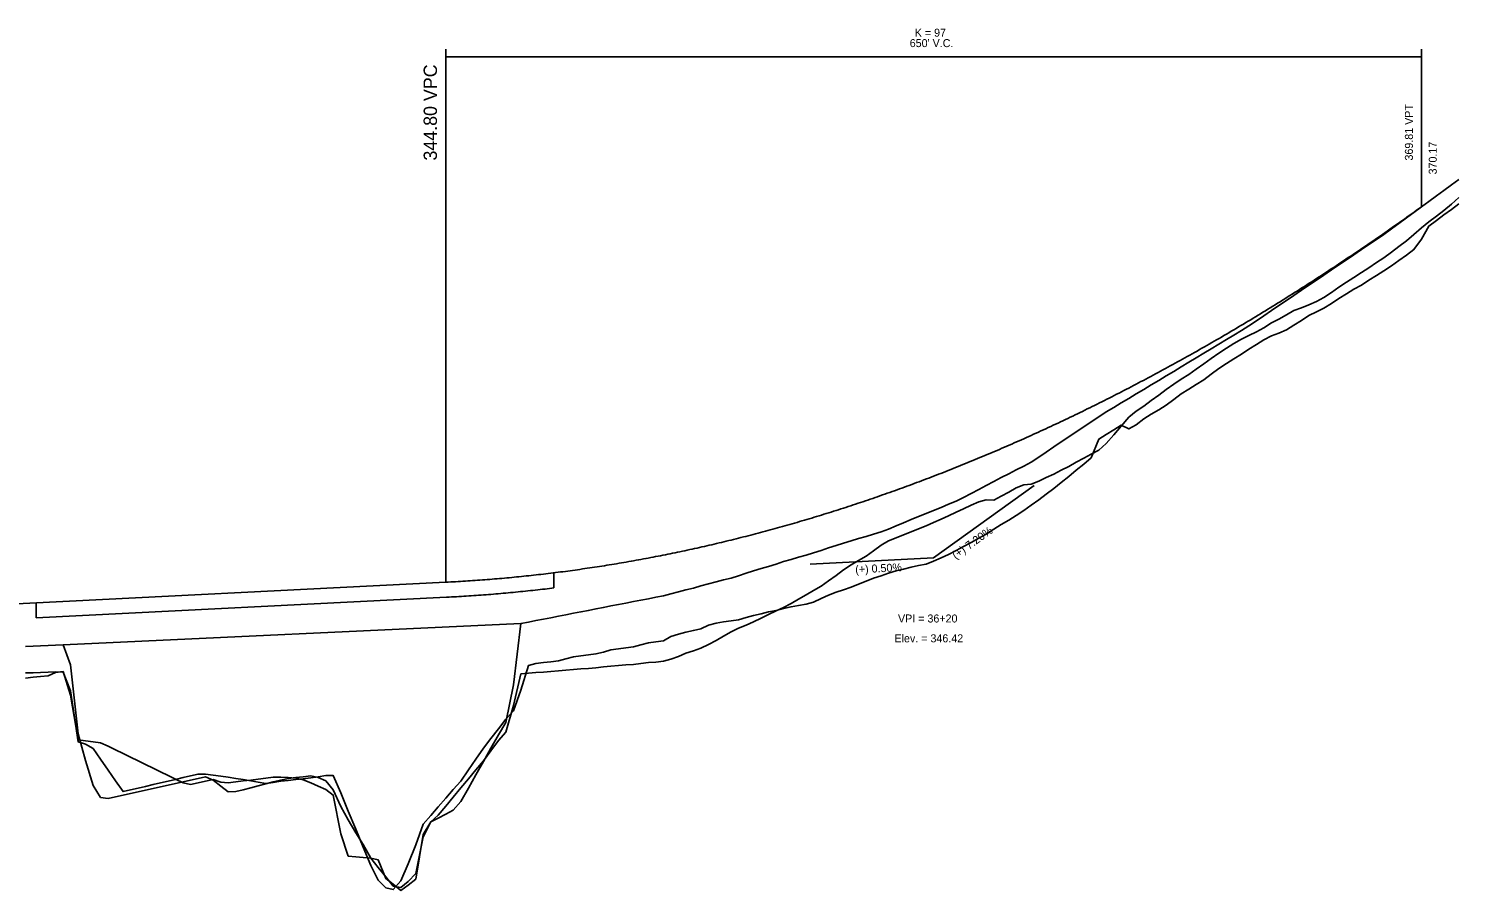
# Model space of a CAD drawing. Extents: x 2005261 to 2010661, y 1001568 to 1006764.
# Drawn here: x 2007639 to 2008591, y 1004311 to 1004885 of the extents above; entities that cross this region are included whole.
import ezdxf

# ---------------------------------------------------------------- set-up
doc = ezdxf.new("R2010")
doc.units = 0
for name, color, linetype in [('RD_DDB_GradeTX', 7, 'Continuous'), ('RD_DDB_Profile_EX', 7, 'Continuous'), ('RD_DDB_Profile_Lbl', 7, 'Continuous'), ('RD_DDB_Profile_PR', 7, 'Continuous'), ('RD_DDB_StripGrade', 7, 'Continuous'), ('RD_DDB_VCLbl', 7, 'Continuous'), ('RD_PD_Bridge', 7, 'Continuous'), ('RD_Sketch1', 7, 'Continuous'), ('RD_Sketch2', 7, 'Continuous'), ('RD_Sketch3', 7, 'Continuous')]:
    doc.layers.add(name, color=color, linetype=linetype)

msp = doc.modelspace()

# ---------------------------------------------------------------- linework, layer by layer
at = {"layer": 'RD_DDB_GradeTX'}
for p in [(2008308.61, 1004580.73), (2008159.44, 1004528.49)]:
    msp.add_line(p, (2008241.73, 1004532.6), dxfattribs=at)
at = {"layer": 'RD_DDB_Profile_EX'}
for points in [[(2008176.73, 1004540.77), (2008181.73, 1004542.33), (2008186.73, 1004543.87), (2008191.73, 1004545.4), (2008196.73, 1004546.9), (2008201.73, 1004548.39), (2008206.73, 1004549.86), (2008211.73, 1004551.71), (2008216.73, 1004553.84), (2008221.73, 1004555.96), (2008226.73, 1004558.06), (2008231.73, 1004560.14), (2008236.73, 1004562.18), (2008241.73, 1004564.23), (2008246.73, 1004566.26), (2008251.73, 1004568.27), (2008256.73, 1004570.27), (2008261.73, 1004572.79), (2008266.73, 1004575.47), (2008271.73, 1004578.14), (2008276.73, 1004580.79), (2008281.73, 1004583.43), (2008286.73, 1004586.04), (2008291.73, 1004588.65), (2008296.73, 1004591.22), (2008301.73, 1004593.75), (2008306.73, 1004596.27), (2008311.73, 1004599.67), (2008316.73, 1004603.1), (2008321.73, 1004606.51), (2008326.73, 1004609.9), (2008331.73, 1004613.27), (2008336.73, 1004616.62), (2008341.73, 1004619.97), (2008346.73, 1004623.32), (2008351.73, 1004626.67), (2008356.73, 1004629.81), (2008361.73, 1004632.81), (2008366.73, 1004635.8), (2008371.73, 1004638.8), (2008376.73, 1004641.79), (2008381.73, 1004644.88), (2008386.73, 1004647.87), (2008391.73, 1004650.87), (2008396.73, 1004653.86), (2008401.73, 1004656.86), (2008406.73, 1004659.94), (2008411.73, 1004662.94), (2008416.73, 1004665.94), (2008421.73, 1004668.93), (2008426.73, 1004671.93), (2008431.73, 1004675.01), (2008436.73, 1004678.01), (2008441.73, 1004681.01), (2008446.73, 1004684), (2008451.73, 1004687.19), (2008456.73, 1004690.58), (2008461.73, 1004693.97), (2008466.73, 1004697.35), (2008471.73, 1004700.74), (2008476.73, 1004704.13), (2008481.73, 1004707.52), (2008486.73, 1004710.9), (2008491.73, 1004714.29), (2008496.73, 1004717.68), (2008501.73, 1004721.07), (2008506.73, 1004724.45), (2008511.73, 1004727.84), (2008516.73, 1004731.22), (2008521.73, 1004734.61), (2008526.73, 1004738), (2008531.73, 1004741.38), (2008536.73, 1004744.77), (2008541.73, 1004748.16), (2008546.73, 1004751.74), (2008551.73, 1004755.41), (2008556.73, 1004759.09), (2008561.73, 1004762.76), (2008566.73, 1004766.43), (2008571.73, 1004770.1), (2008576.73, 1004773.77), (2008581.73, 1004777.45), (2008586.73, 1004781.12), (2008591.73, 1004784.79)], [(2007676.73, 1004397.66), (2007681.73, 1004380.82), (2007686.73, 1004372.92), (2007691.73, 1004372.21), (2007696.73, 1004373.33), (2007701.73, 1004374.44), (2007706.73, 1004375.56), (2007711.73, 1004376.68), (2007716.73, 1004377.8), (2007721.73, 1004378.92), (2007726.73, 1004380.04), (2007731.73, 1004381.16), (2007736.73, 1004382.28), (2007741.73, 1004383.4), (2007746.73, 1004384.52), (2007751.73, 1004385.64), (2007756.73, 1004386.76), (2007761.73, 1004384.37), (2007766.73, 1004380.41), (2007771.73, 1004376.78), (2007776.73, 1004376.81), (2007781.73, 1004378.1), (2007786.73, 1004379.39), (2007791.73, 1004380.68), (2007796.73, 1004381.98), (2007801.73, 1004383.27), (2007806.73, 1004384.56), (2007811.73, 1004385.65), (2007816.73, 1004386.19), (2007821.73, 1004386.74), (2007826.73, 1004387.28), (2007831.73, 1004386.19), (2007836.73, 1004384.09), (2007841.73, 1004378.09), (2007846.73, 1004366.91), (2007851.73, 1004358.02), (2007856.73, 1004349.39), (2007861.73, 1004341.53), (2007866.73, 1004332.4), (2007871.73, 1004326.16), (2007876.73, 1004319.93), (2007881.73, 1004313.72), (2007886.73, 1004312.86), (2007891.73, 1004317.03), (2007896.73, 1004322.2), (2007901.73, 1004346.77), (2007906.73, 1004356.58), (2007911.73, 1004359.23), (2007916.73, 1004361.87), (2007921.73, 1004364.52), (2007926.73, 1004370.26), (2007931.73, 1004379.08), (2007936.73, 1004387.96), (2007941.73, 1004396.84), (2007946.73, 1004405.72), (2007951.73, 1004414.6), (2007956.73, 1004422.79), (2007961.73, 1004448.01), (2007966.73, 1004488.86), (2007971.73, 1004489.77), (2007976.73, 1004490.75), (2007981.73, 1004491.73), (2007986.73, 1004492.71), (2007991.73, 1004493.68), (2007996.73, 1004494.64), (2008001.73, 1004495.63), (2008006.73, 1004496.61), (2008011.73, 1004497.6), (2008016.73, 1004498.58), (2008021.73, 1004499.57), (2008026.73, 1004500.54), (2008031.73, 1004501.5), (2008036.73, 1004502.47), (2008041.73, 1004503.44), (2008046.73, 1004504.42), (2008051.73, 1004505.39), (2008056.73, 1004506.36), (2008061.73, 1004507.33), (2008066.73, 1004508.6), (2008071.73, 1004509.9), (2008076.73, 1004511.19), (2008081.73, 1004512.49), (2008086.73, 1004513.96), (2008091.73, 1004515.28), (2008096.73, 1004516.57), (2008101.73, 1004517.86), (2008106.73, 1004519.14), (2008111.73, 1004520.65), (2008116.73, 1004522.33), (2008121.73, 1004523.88), (2008126.73, 1004525.41), (2008131.73, 1004526.93), (2008136.73, 1004528.47), (2008141.73, 1004530.09), (2008146.73, 1004531.57), (2008151.73, 1004533.03), (2008156.73, 1004534.47), (2008161.73, 1004535.93), (2008166.73, 1004537.6), (2008171.73, 1004539.19), (2008176.73, 1004540.77)], [(2007636.73, 1004473.47), (2007641.73, 1004473.71), (2007646.73, 1004473.96), (2007651.73, 1004474.2), (2007656.73, 1004474.43), (2007661.73, 1004474.68), (2007666.73, 1004461.35), (2007671.73, 1004415.33), (2007676.73, 1004397.66)]]:
    msp.add_lwpolyline(points, dxfattribs=at)
at = {"layer": 'RD_DDB_Profile_PR'}
for p, q in [((2008566.73, 1004766.5), (2008571.73, 1004770.1)), ((2007331.73, 1004487.1), (2007916.73, 1004516.35))]:
    msp.add_line(p, q, dxfattribs=at)
msp.add_spline([(2007916.73, 1004516.35), (2007929.73, 1004517.09), (2007942.73, 1004518), (2007955.73, 1004519.08), (2007968.73, 1004520.34), (2007981.73, 1004521.78), (2007994.73, 1004523.38), (2008007.73, 1004525.17), (2008020.73, 1004527.12), (2008033.73, 1004529.25), (2008046.73, 1004531.56), (2008059.73, 1004534.03), (2008072.73, 1004536.69), (2008085.73, 1004539.51), (2008098.73, 1004542.51), (2008111.73, 1004545.69), (2008124.73, 1004549.04), (2008137.73, 1004552.56), (2008150.73, 1004556.26), (2008163.73, 1004560.13), (2008176.73, 1004564.17), (2008189.73, 1004568.39), (2008202.73, 1004572.79), (2008215.73, 1004577.35), (2008228.73, 1004582.1), (2008241.73, 1004587.01), (2008254.73, 1004592.1), (2008267.73, 1004597.37), (2008280.73, 1004602.8), (2008293.73, 1004608.42), (2008306.73, 1004614.2), (2008319.73, 1004620.16), (2008332.73, 1004626.3), (2008345.73, 1004632.61), (2008358.73, 1004639.09), (2008371.73, 1004645.75), (2008384.73, 1004652.58), (2008397.73, 1004659.58), (2008410.73, 1004666.76), (2008423.73, 1004674.12), (2008436.73, 1004681.65), (2008449.73, 1004689.35), (2008462.73, 1004697.22), (2008475.73, 1004705.27), (2008488.73, 1004713.5), (2008501.73, 1004721.9), (2008514.73, 1004730.47), (2008527.73, 1004739.21), (2008540.73, 1004748.13), (2008553.73, 1004757.23), (2008566.73, 1004766.5)], degree=3, dxfattribs=at)
at = {"layer": 'RD_DDB_VCLbl'}
for p, q in [((2007916.73, 1004871.5), (2007916.73, 1004516.35)), ((2007916.73, 1004866.5), (2008566.73, 1004866.5)), ((2008566.73, 1004871.5), (2008566.73, 1004766.5))]:
    msp.add_line(p, q, dxfattribs=at)
at = {"layer": 'RD_PD_Bridge'}
for p, q in [((2007988.73, 1004512.54), (2007988.73, 1004522.62)), ((2007643.73, 1004492.69), (2007917.23, 1004506.36)), ((2007643.73, 1004492.69), (2007643.73, 1004502.7))]:
    msp.add_line(p, q, dxfattribs=at)
msp.add_spline([(2007917.3, 1004506.37), (2007930.37, 1004507.11), (2007943.5, 1004508.03), (2007956.63, 1004509.12), (2007969.76, 1004510.4), (2007982.89, 1004511.84), (2007988.73, 1004512.54)], degree=3, dxfattribs=at)
at = {"layer": 'RD_Sketch1'}
msp.add_line((2007661.73, 1004474.68), (2007966.73, 1004488.86), dxfattribs=at)
at = {"layer": 'RD_Sketch2'}
for points in [[(2008176.73, 1004520.91), (2008181.73, 1004524.65), (2008186.73, 1004527.95), (2008191.73, 1004530.76), (2008196.73, 1004533.64), (2008201.73, 1004537.27), (2008206.73, 1004541.07), (2008211.73, 1004544), (2008216.73, 1004546.02), (2008221.73, 1004547.94), (2008226.73, 1004549.9), (2008231.73, 1004551.92), (2008236.73, 1004553.99), (2008241.73, 1004556.11), (2008246.73, 1004558.29), (2008251.73, 1004560.62), (2008256.73, 1004563.03), (2008261.73, 1004565.32), (2008266.73, 1004567.62), (2008271.73, 1004569.96), (2008276.73, 1004571.17), (2008281.73, 1004571.12), (2008286.73, 1004573.64), (2008291.73, 1004576.44), (2008296.73, 1004579.32), (2008301.73, 1004581.35), (2008306.73, 1004581.69), (2008311.73, 1004583.72), (2008316.73, 1004586.04), (2008321.73, 1004588.47), (2008326.73, 1004590.99), (2008331.73, 1004593.58), (2008336.73, 1004596.32), (2008341.73, 1004599.04), (2008346.73, 1004601.76), (2008351.73, 1004604.43), (2008356.73, 1004608.8), (2008361.73, 1004614.62), (2008366.73, 1004620.44), (2008371.73, 1004626.26), (2008376.73, 1004630.27), (2008381.73, 1004633.77), (2008386.73, 1004637.41), (2008391.73, 1004641.06), (2008396.73, 1004644.7), (2008401.73, 1004648.34), (2008406.73, 1004651.58), (2008411.73, 1004654.81), (2008416.73, 1004658.35), (2008421.73, 1004661.89), (2008426.73, 1004665.42), (2008431.73, 1004668.96), (2008436.73, 1004672.37), (2008441.73, 1004675.43), (2008446.73, 1004678.27), (2008451.73, 1004680.72), (2008456.73, 1004683.18), (2008461.73, 1004685.92), (2008466.73, 1004689.23), (2008471.73, 1004691.72), (2008476.73, 1004694.52), (2008481.73, 1004697.35), (2008486.73, 1004699.3), (2008491.73, 1004701.26), (2008496.73, 1004703.32), (2008501.73, 1004706.02), (2008506.73, 1004709.43), (2008511.73, 1004712.9), (2008516.73, 1004716.32), (2008521.73, 1004719.49), (2008526.73, 1004722.65), (2008531.73, 1004725.95), (2008536.73, 1004729.33), (2008541.73, 1004732.58), (2008546.73, 1004736.21), (2008551.73, 1004740.03), (2008556.73, 1004743.85), (2008561.73, 1004748.17), (2008566.73, 1004752.52), (2008571.73, 1004756.49), (2008576.73, 1004760.31), (2008581.73, 1004764.13), (2008586.73, 1004768.38), (2008591.73, 1004772.7)], [(2007676.73, 1004410.68), (2007681.73, 1004410), (2007686.73, 1004409.33), (2007691.73, 1004407.22), (2007696.73, 1004404.76), (2007701.73, 1004402.3), (2007706.73, 1004399.83), (2007711.73, 1004397.37), (2007716.73, 1004394.91), (2007721.73, 1004392.44), (2007726.73, 1004389.98), (2007731.73, 1004387.52), (2007736.73, 1004385.06), (2007741.73, 1004382.59), (2007746.73, 1004381.57), (2007751.73, 1004382.69), (2007756.73, 1004383.81), (2007761.73, 1004384.93), (2007766.73, 1004383.1), (2007771.73, 1004382.61), (2007776.73, 1004383.26), (2007781.73, 1004383.91), (2007786.73, 1004384.56), (2007791.73, 1004385.22), (2007796.73, 1004385.87), (2007801.73, 1004386.49), (2007806.73, 1004386.36), (2007811.73, 1004386.16), (2007816.73, 1004385.86), (2007821.73, 1004384.76), (2007826.73, 1004382.61), (2007831.73, 1004380.47), (2007836.73, 1004378.32), (2007841.73, 1004374.54), (2007846.73, 1004348.76), (2007851.73, 1004333.87), (2007856.73, 1004333.43), (2007861.73, 1004333), (2007866.73, 1004332.56), (2007871.73, 1004331.27), (2007876.73, 1004318.85), (2007881.73, 1004315.2), (2007886.73, 1004310.98), (2007891.73, 1004314.54), (2007896.73, 1004318.59), (2007901.73, 1004348.23), (2007906.73, 1004356.7), (2007911.73, 1004361.09), (2007916.73, 1004367.14), (2007921.73, 1004373.2), (2007926.73, 1004379.26), (2007931.73, 1004385.32), (2007936.73, 1004391.37), (2007941.73, 1004397.43), (2007946.73, 1004403.99), (2007951.73, 1004410.88), (2007956.73, 1004416.43), (2007961.73, 1004434.11), (2007966.73, 1004455.2), (2007971.73, 1004455.73), (2007976.73, 1004456.09), (2007981.73, 1004456.46), (2007986.73, 1004456.82), (2007991.73, 1004457.2), (2007996.73, 1004457.75), (2008001.73, 1004458.19), (2008006.73, 1004458.57), (2008011.73, 1004458.95), (2008016.73, 1004459.34), (2008021.73, 1004459.91), (2008026.73, 1004460.43), (2008031.73, 1004460.82), (2008036.73, 1004461.21), (2008041.73, 1004461.62), (2008046.73, 1004462.2), (2008051.73, 1004462.77), (2008056.73, 1004463.17), (2008061.73, 1004463.66), (2008066.73, 1004465.07), (2008071.73, 1004466.96), (2008076.73, 1004468.98), (2008081.73, 1004470.74), (2008086.73, 1004472.4), (2008091.73, 1004474.85), (2008096.73, 1004477.53), (2008101.73, 1004480.33), (2008106.73, 1004483.26), (2008111.73, 1004485.68), (2008116.73, 1004487.76), (2008121.73, 1004489.99), (2008126.73, 1004492.36), (2008131.73, 1004494.82), (2008136.73, 1004497.37), (2008141.73, 1004499.55), (2008146.73, 1004502.27), (2008151.73, 1004505.08), (2008156.73, 1004507.97), (2008161.73, 1004510.8), (2008166.73, 1004513.64), (2008171.73, 1004517.24), (2008176.73, 1004520.91)], [(2007636.73, 1004452.4), (2007641.73, 1004452.98), (2007646.73, 1004453.56), (2007651.73, 1004454.03), (2007656.73, 1004456.25), (2007661.73, 1004456.77), (2007666.73, 1004441.06), (2007671.73, 1004411.35), (2007676.73, 1004410.68)]]:
    msp.add_lwpolyline(points, dxfattribs=at)
at = {"layer": 'RD_Sketch3'}
for points in [[(2008176.73, 1004509.71), (2008181.73, 1004511.33), (2008186.73, 1004513.06), (2008191.73, 1004515.1), (2008196.73, 1004517.07), (2008201.73, 1004518.99), (2008206.73, 1004520.55), (2008211.73, 1004522.36), (2008216.73, 1004523.92), (2008221.73, 1004525.16), (2008226.73, 1004526.33), (2008231.73, 1004527.43), (2008236.73, 1004528.46), (2008241.73, 1004530.34), (2008246.73, 1004532.58), (2008251.73, 1004534.86), (2008256.73, 1004537.55), (2008261.73, 1004540.23), (2008266.73, 1004542.92), (2008271.73, 1004545.65), (2008276.73, 1004548.49), (2008281.73, 1004551.78), (2008286.73, 1004554.85), (2008291.73, 1004557.8), (2008296.73, 1004560.82), (2008301.73, 1004564.09), (2008306.73, 1004567.71), (2008311.73, 1004571.37), (2008316.73, 1004575.1), (2008321.73, 1004578.91), (2008326.73, 1004582.83), (2008331.73, 1004586.86), (2008336.73, 1004590.96), (2008341.73, 1004595.06), (2008346.73, 1004599.25), (2008351.73, 1004611.7), (2008356.73, 1004614.8), (2008361.73, 1004617.89), (2008366.73, 1004620.93), (2008371.73, 1004618.52), (2008376.73, 1004621.3), (2008381.73, 1004625.16), (2008386.73, 1004628.27), (2008391.73, 1004631.31), (2008396.73, 1004634.35), (2008401.73, 1004638.01), (2008406.73, 1004641.79), (2008411.73, 1004645.09), (2008416.73, 1004648.2), (2008421.73, 1004651.32), (2008426.73, 1004654.96), (2008431.73, 1004658.69), (2008436.73, 1004662.09), (2008441.73, 1004665.26), (2008446.73, 1004668.43), (2008451.73, 1004671.77), (2008456.73, 1004674.85), (2008461.73, 1004677.94), (2008466.73, 1004680.45), (2008471.73, 1004682.31), (2008476.73, 1004684.47), (2008481.73, 1004687.65), (2008486.73, 1004690.82), (2008491.73, 1004694), (2008496.73, 1004696.47), (2008501.73, 1004698.92), (2008506.73, 1004702.15), (2008511.73, 1004705.38), (2008516.73, 1004708.61), (2008521.73, 1004711.64), (2008526.73, 1004714.29), (2008531.73, 1004717.56), (2008536.73, 1004720.83), (2008541.73, 1004723.93), (2008546.73, 1004727.26), (2008551.73, 1004730.83), (2008556.73, 1004734.4), (2008561.73, 1004737.97), (2008566.73, 1004744.91), (2008571.73, 1004753.69), (2008576.73, 1004757.38), (2008581.73, 1004761.08), (2008586.73, 1004764.77), (2008591.73, 1004768.46)], [(2007676.73, 1004408.45), (2007681.73, 1004405.55), (2007686.73, 1004398.36), (2007691.73, 1004391.18), (2007696.73, 1004384), (2007701.73, 1004376.82), (2007706.73, 1004377.99), (2007711.73, 1004379.15), (2007716.73, 1004380.32), (2007721.73, 1004381.49), (2007726.73, 1004382.66), (2007731.73, 1004383.83), (2007736.73, 1004385), (2007741.73, 1004386.17), (2007746.73, 1004387.34), (2007751.73, 1004388.5), (2007756.73, 1004388.43), (2007761.73, 1004387.81), (2007766.73, 1004387.18), (2007771.73, 1004386.44), (2007776.73, 1004385.62), (2007781.73, 1004384.8), (2007786.73, 1004383.98), (2007791.73, 1004383.16), (2007796.73, 1004382.34), (2007801.73, 1004382.94), (2007806.73, 1004383.8), (2007811.73, 1004384.34), (2007816.73, 1004384.89), (2007821.73, 1004385.44), (2007826.73, 1004385.99), (2007831.73, 1004386.77), (2007836.73, 1004387.56), (2007841.73, 1004387.53), (2007846.73, 1004375.99), (2007851.73, 1004363.89), (2007856.73, 1004351.8), (2007861.73, 1004339.71), (2007866.73, 1004327.62), (2007871.73, 1004317.91), (2007876.73, 1004312.79), (2007881.73, 1004311.56), (2007886.73, 1004317.42), (2007891.73, 1004328.67), (2007896.73, 1004341.35), (2007901.73, 1004355.11), (2007906.73, 1004360.91), (2007911.73, 1004366.71), (2007916.73, 1004372.51), (2007921.73, 1004378.31), (2007926.73, 1004383.88), (2007931.73, 1004391.29), (2007936.73, 1004398.54), (2007941.73, 1004405.67), (2007946.73, 1004412.14), (2007951.73, 1004418.61), (2007956.73, 1004425.08), (2007961.73, 1004430.7), (2007966.73, 1004444.49), (2007971.73, 1004460.85), (2007976.73, 1004462.27), (2007981.73, 1004462.83), (2007986.73, 1004463.4), (2007991.73, 1004463.97), (2007996.73, 1004465.23), (2008001.73, 1004466.7), (2008006.73, 1004467.33), (2008011.73, 1004467.96), (2008016.73, 1004468.58), (2008021.73, 1004469.85), (2008026.73, 1004471.34), (2008031.73, 1004472.02), (2008036.73, 1004472.7), (2008041.73, 1004473.37), (2008046.73, 1004474.64), (2008051.73, 1004475.94), (2008056.73, 1004476.65), (2008061.73, 1004477.28), (2008066.73, 1004480.21), (2008071.73, 1004481.79), (2008076.73, 1004483.04), (2008081.73, 1004484.2), (2008086.73, 1004485.28), (2008091.73, 1004487.81), (2008096.73, 1004489.12), (2008101.73, 1004489.93), (2008106.73, 1004490.67), (2008111.73, 1004491.33), (2008116.73, 1004492.82), (2008121.73, 1004494.18), (2008126.73, 1004495.39), (2008131.73, 1004496.54), (2008136.73, 1004497.62), (2008141.73, 1004498.82), (2008146.73, 1004499.98), (2008151.73, 1004500.91), (2008156.73, 1004501.74), (2008161.73, 1004503.16), (2008166.73, 1004505.44), (2008171.73, 1004507.64), (2008176.73, 1004509.71)], [(2007636.73, 1004455.95), (2007641.73, 1004456.06), (2007646.73, 1004456.25), (2007651.73, 1004456.44), (2007656.73, 1004456.57), (2007661.73, 1004456.49), (2007666.73, 1004444.09), (2007671.73, 1004410.02), (2007676.73, 1004408.45)]]:
    msp.add_lwpolyline(points, dxfattribs=at)

# ---------------------------------------------------------------- texts
at = {"layer": 'RD_DDB_GradeTX'}
for s, rotation, p in [('(+) 7.20%', 35.74208, (2008256.4, 1004531.48)), ('(+) 0.50%', 2.86241, (2008189.63, 1004522.18))]:
    msp.add_text(s, height=5.331, rotation=rotation, dxfattribs=at).set_placement(p)
at = {"layer": 'RD_DDB_Profile_Lbl'}
msp.add_text('370.17', height=5.331, rotation=90, dxfattribs=at).set_placement((2008576.91, 1004788.1))
for s, p in [('VPI = 36+20', (2008217.98, 1004489.52)), ('Elev. = 346.42', (2008215.63, 1004476.31))]:
    msp.add_text(s, height=5.3312, dxfattribs=at).set_placement(p)
at = {"layer": 'RD_DDB_StripGrade'}
for s, height, p in [('344.80 VPC', 8.882, (2007910.83, 1004797.35)), ('369.81 VPT', 5.331, (2008561.03, 1004797.35))]:
    msp.add_text(s, height=height, rotation=90, dxfattribs=at).set_placement(p)
at = {"layer": 'RD_DDB_VCLbl'}
for s, p in [('K = 97', (2008229.15, 1004879.88)), ("650' V.C.", (2008225.8, 1004872.95))]:
    msp.add_text(s, height=5.331, dxfattribs=at).set_placement(p)

doc.saveas('drawing.dxf')
